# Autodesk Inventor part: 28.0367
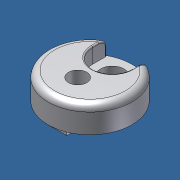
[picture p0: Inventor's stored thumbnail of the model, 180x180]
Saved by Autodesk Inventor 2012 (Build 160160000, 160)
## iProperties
Created: 2014-04
Part Number: 28.0367
Material: Default
Document SubType Name: Modeling
Designer: Admin
Density: 1 g/cm^3
Description: MINI ADJ BEARING SUP. HANDLE 32
Mass: 6.20123 g
Surface Area: 28.1034 cm^2
Volume: 6.20123 cm^3
Vendor: S
Translation Standard: STEP AP214IS
FileName: 28-0367-0.stp
PreProcessor: Mechanical Desktop 2011
PostProcessor: Build: 160, Release: 2012 RTM - Date: Tue 03/01/2011
Sent Units: inch
Uncertainty: 1.0000000000000002e-06
Author: Admin
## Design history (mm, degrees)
node "Product1"
node "Base1"
body "Solid1"
